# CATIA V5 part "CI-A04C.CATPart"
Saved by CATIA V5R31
Part number: CI-A04C
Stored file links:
  C:\Users\simone\Dropbox\3DTECH\Cassina - Catalogo Custom Interiors\MODELLI 3D\DEFINITIVI\ESPORTATI\CI-A04C SEDIA OUTDOOR SENZA BRACCIOLI\CI-A04C.CATPart

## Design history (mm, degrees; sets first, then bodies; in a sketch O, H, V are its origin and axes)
Set1
  Point1 "Point.1": stored without definition
  DatumCurve1 "Curve.1"
  DatumCurve2 "Curve.2"
  DatumCurve3 "Curve.3"
  DatumCurve4 "Curve.4"
Body1 "Solid13" (main body)
  Solid1: solid without history
Body2 "Solid26"
  Solid2: solid without history
Body3 "Solid28"
  Solid3: solid without history
Body4 "Solid35"
  Solid4: solid without history
Body5 "Solid36"
  Solid5: solid without history
Body6 "Solid45"
  Solid6: solid without history
Body7 "Solido47"
  Solid7: solid without history
Body8 "piedini frontali"
  Solid8: solid without history
Body9 "piedini retro"
  Solid9: solid without history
